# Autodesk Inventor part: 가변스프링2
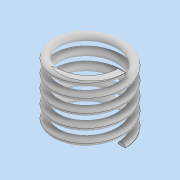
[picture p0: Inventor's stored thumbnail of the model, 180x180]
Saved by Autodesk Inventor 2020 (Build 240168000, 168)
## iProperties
Created: 2021-10
Part Number: 가변스프링2
Material: 일반
Document SubType Name: Modeling
Designer: user
Density: 1 g/cm^3
Appearance: 기본값
Mass: 0.824199 g
Surface Area: 16.7339 cm^2
Volume: 0.824199 cm^3
Author: user
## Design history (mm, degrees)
sketch "스케치1"
  geometry: L1 (0, 0)-(8.5, 0); L2 (8.5, 0)-(8.5, 17.5); L3 (8.5, 17.5)-(0, 17.5); L4 (0, 17.5)-(0, 0); C1 r 1 at (8.5, 17.5)
  constraints: 8 end point, 2 parallel, 1 centre point, 1 coincident, 1 horizontal, 1 perpendicular
  dimensions: "d0" = 2 diameter of C1; "d1" = 17 diameter of L2 L4; "d2" = 17.5 distance between parallel lines of L1 L3 (derived)
feature "코일1" sketch "스케치1" pitch "d3" = 10; turns "d5" = 5; dims "d4" = 17.5 (= d2), "d6" = 0, angle "d7" = 90 deg, angle "d8" = 90 deg, "d9" = 0, "d10" = 0
sketch "스케치2"
  geometry: L1 (17.5, 11.854)-(0, 11.854); L2 (0, 11.854)-(0, -11.854); L3 (0, -11.854)-(17.5, -11.854); L4 (17.5, -11.854)-(17.5, 11.854); 2 further points
  constraints: 8 end point, 2 parallel, 1 coincident, 1 horizontal, 1 midpoint, 1 perpendicular
  dimensions: "d11" = 17.5 distance between parallel lines of L2 L4 (= d2)
extrude "돌출1" sketch "스케치2" stored distance "d12" = 32.5; taper "d13" = 0 deg
node "솔리드1"
